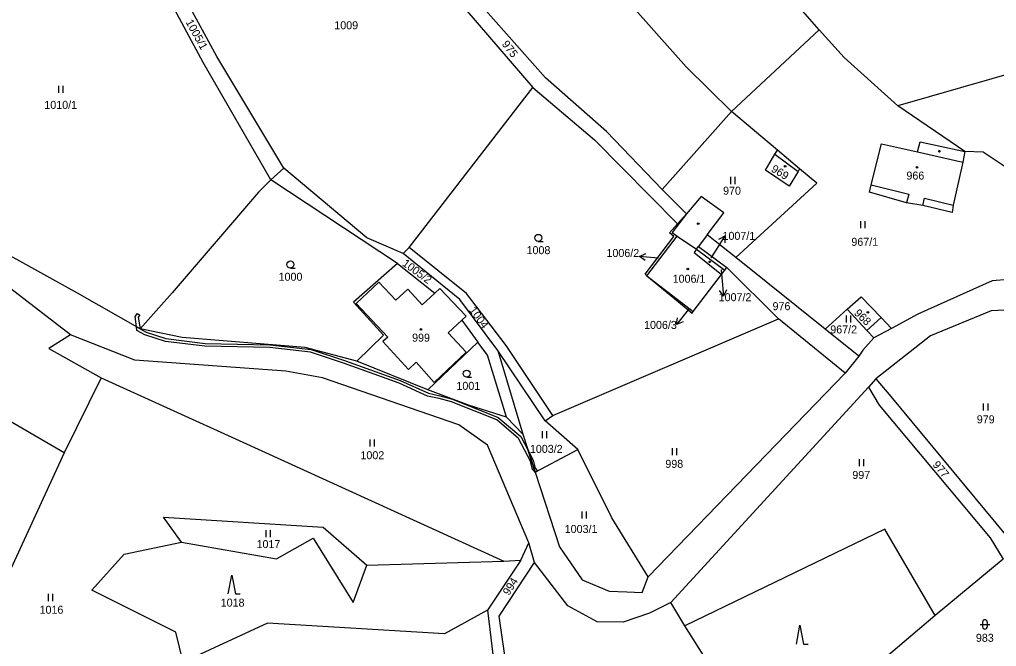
# Model space of a CAD drawing. Extents: x -670359 to -668019, y -978807 to -976674.
# Drawn here: x -669783.1 to -669575.5, y -977704.1 to -977570.9 of the extents above; entities that cross this region are included whole.
import ezdxf

# ---------------------------------------------------------------- set-up
doc = ezdxf.new("R2010")
doc.units = 0
for name, color, linetype in [('Hranice parcel', 7, 'Continuous'), ('Parcelní čísla', 7, 'Continuous'), ('Vnitřní kresba', 7, 'Continuous'), ('Věcná břemena k části', 7, 'Continuous'), ('Značky budov', 7, 'Continuous'), ('Značky kultur', 7, 'Continuous')]:
    doc.layers.add(name, color=color, linetype=linetype)

msp = doc.modelspace()

# ---------------------------------------------------------------- linework, layer by layer
at = {"layer": 'Hranice parcel'}
for p, q in [((-669702.8, -977622.71), (-669694.86, -977629.03)), ((-669694.86, -977629.03), (-669693.79, -977628.05)), ((-669693.79, -977628.05), (-669688.21, -977633.93)), ((-669688.21, -977633.93), (-669689.13, -977634.79)), ((-669689.13, -977634.79), (-669685.71, -977639.46))]:
    msp.add_line(p, q, dxfattribs=at)
for points in [[(-669741.19, -977578.75), (-669756.29, -977550.87)], [(-669613.14, -977573.11), (-669632.98, -977550.37)], [(-669744.06, -977580.04), (-669759.08, -977552.08)], [(-669641.45, -977580.95), (-669662.61, -977557.1)], [(-669690.63, -977565.98), (-669673.98, -977585.38)], [(-669671.35, -977583.28), (-669687.92, -977564.52)], [(-669631.8, -977590.48), (-669613.14, -977573.11)], [(-669607.88, -977578.99), (-669613.14, -977573.11)], [(-669729.69, -977604.97), (-669744.06, -977580.04)], [(-669726.9, -977602.47), (-669741.19, -977578.75)], [(-669596.46, -977589.23), (-669607.88, -977578.99)], [(-669563.17, -977579.68), (-669596.46, -977589.23)], [(-669631.8, -977590.48), (-669641.45, -977580.95)], [(-669658.33, -977594.71), (-669671.35, -977583.28)], [(-669700.29, -977619.32), (-669673.98, -977585.38)], [(-669673.98, -977585.38), (-669660.88, -977596.49)], [(-669631.8, -977590.48), (-669646.51, -977607.03)], [(-669622.05, -977598.67), (-669631.8, -977590.48)], [(-669582.18, -977598.97), (-669596.46, -977589.23)], [(-669646.51, -977607.03), (-669658.33, -977594.71)], [(-669660.88, -977596.49), (-669643.3, -977614.32)], [(-669592.25, -977599.03), (-669591.7, -977596.87)], [(-669591.7, -977596.87), (-669582.18, -977598.97)], [(-669622.56, -977599.53), (-669622.05, -977598.67)], [(-669617.33, -977602.63), (-669622.05, -977598.67)], [(-669602.13, -977606.04), (-669599.94, -977597.32)], [(-669599.94, -977597.32), (-669592.25, -977599.03)], [(-669582.18, -977598.97), (-669582.61, -977601.23)], [(-669578.34, -977599.11), (-669582.18, -977598.97)], [(-669546.47, -977620.34), (-669578.34, -977599.11)], [(-669624.54, -977602.9), (-669622.56, -977599.53)], [(-669582.61, -977601.23), (-669584.67, -977610.34)], [(-669729.69, -977604.97), (-669726.9, -977602.47)], [(-669709.26, -977617.28), (-669726.9, -977602.47)], [(-669619.56, -977606.31), (-669624.54, -977602.9)], [(-669617.66, -977603.18), (-669619.56, -977606.31)], [(-669617.33, -977602.63), (-669617.66, -977603.18)], [(-669613.65, -977605.71), (-669617.33, -977602.63)], [(-669729.69, -977604.97), (-669732.31, -977607.62)], [(-669702.8, -977622.71), (-669729.69, -977604.97)], [(-669641.36, -977612.19), (-669646.51, -977607.03)], [(-669630.9, -977621.45), (-669613.65, -977605.71)], [(-669602.44, -977607.57), (-669602.13, -977606.04)], [(-669732.31, -977607.62), (-669750.67, -977628.99)], [(-669638.26, -977608.5), (-669641.36, -977612.19)], [(-669633.45, -977611.99), (-669638.26, -977608.5)], [(-669594.59, -977609.84), (-669602.44, -977607.57)], [(-669591.15, -977610.45), (-669594.59, -977609.84)], [(-669584.91, -977611.94), (-669591.15, -977610.45)], [(-669584.67, -977610.34), (-669584.91, -977611.94)], [(-669641.36, -977612.19), (-669644.37, -977616.17)], [(-669643.3, -977614.32), (-669641.36, -977612.19)], [(-669636.94, -977616.64), (-669633.45, -977611.99)], [(-669644.94, -977616.21), (-669643.3, -977614.32)], [(-669701.58, -977620.62), (-669709.26, -977617.28)], [(-669650.15, -977625.03), (-669644.06, -977617)], [(-669649.75, -977625.36), (-669643.33, -977616.96)], [(-669644.06, -977617), (-669644.94, -977616.21)], [(-669644.37, -977616.17), (-669643.33, -977616.96)], [(-669636.94, -977616.64), (-669638.77, -977619.13)], [(-669630.9, -977621.45), (-669636.94, -977616.64)], [(-669770.74, -977629.03), (-669788.31, -977619.38)], [(-669701.58, -977620.62), (-669700.29, -977619.32)], [(-669688.13, -977629.14), (-669700.29, -977619.32)], [(-669639.2, -977619.73), (-669639.7, -977620.4), (-669633.91, -977625.07)], [(-669639.2, -977619.73), (-669638.77, -977619.13)], [(-669639.2, -977619.73), (-669633.19, -977624.13)], [(-669638.77, -977619.13), (-669632.78, -977623.59)], [(-669689.55, -977630.42), (-669701.58, -977620.62)], [(-669611.88, -977636.68), (-669630.9, -977621.45)], [(-669702.8, -977622.71), (-669712.12, -977630.99)], [(-669633.91, -977625.07), (-669633.19, -977624.13)], [(-669633.19, -977624.13), (-669632.78, -977623.59)], [(-669632.78, -977623.59), (-669621.84, -977634.48)], [(-669650.15, -977625.03), (-669649.75, -977625.36)], [(-669649.75, -977625.36), (-669644.66, -977629.57), (-669640.16, -977633.27)], [(-669649.75, -977625.36), (-669639.91, -977632.94)], [(-669639.91, -977632.94), (-669633.91, -977625.07)], [(-669562.52, -977625.31), (-669576.43, -977626.43)], [(-669772.22, -977637.91), (-669784.93, -977628.12)], [(-669576.43, -977626.43), (-669592.23, -977633.48)], [(-669757.47, -977636.62), (-669770.74, -977629.03)], [(-669750.67, -977628.99), (-669757.47, -977636.62)], [(-669679.67, -977640.17), (-669688.13, -977629.14)], [(-669607.19, -977632.45), (-669604.24, -977629.79)], [(-669604.24, -977629.79), (-669599.98, -977634.24)], [(-669712.12, -977630.99), (-669705.76, -977637.99)], [(-669681.42, -977641.23), (-669689.55, -977630.42)], [(-669564, -977632.19), (-669576.64, -977632.82)], [(-669669.73, -977655.05), (-669621.84, -977634.48)], [(-669640.16, -977633.27), (-669639.91, -977632.94)], [(-669607.67, -977646.03), (-669621.84, -977634.48)], [(-669611.88, -977636.68), (-669607.19, -977632.45)], [(-669603, -977636.98), (-669607.19, -977632.45)], [(-669599.98, -977634.24), (-669597.8, -977636.52)], [(-669592.23, -977633.48), (-669597.8, -977636.52)], [(-669576.64, -977632.82), (-669589.48, -977638.09)], [(-669597.8, -977636.52), (-669601.54, -977638.56)], [(-669772.22, -977637.91), (-669776.84, -977640.81)], [(-669758.59, -977643.26), (-669772.22, -977637.91)], [(-669748.54, -977638.48), (-669757.47, -977636.62)], [(-669722.38, -977640.57), (-669748.54, -977638.48)], [(-669705.76, -977637.99), (-669711.41, -977643.46)], [(-669604.71, -977642.43), (-669611.88, -977636.68)], [(-669601.54, -977638.56), (-669603.86, -977641.14)], [(-669601.54, -977638.56), (-669603, -977636.98)], [(-669589.48, -977638.09), (-669601.11, -977647.27)], [(-669716.21, -977642.21), (-669722.38, -977640.57)], [(-669685.71, -977639.46), (-669696.32, -977649.6)], [(-669683.67, -977642.25), (-669685.71, -977639.46)], [(-669669.73, -977655.05), (-669679.67, -977640.17)], [(-669773.6, -977662.93), (-669808.82, -977642.52)], [(-669776.84, -977640.81), (-669765.77, -977647.06)], [(-669711.41, -977643.46), (-669716.21, -977642.21)], [(-669679.6, -977655.41), (-669683.67, -977642.25)], [(-669671.39, -977656.17), (-669681.42, -977641.23)], [(-669681.42, -977641.23), (-669676.14, -977658.99)], [(-669604.71, -977642.43), (-669607.67, -977646.03)], [(-669603.86, -977641.14), (-669604.71, -977642.43)], [(-669726.51, -977645.62), (-669758.59, -977643.26)], [(-669696.32, -977649.6), (-669711.41, -977643.46)], [(-669718.67, -977647.02), (-669726.51, -977645.62)], [(-669607.67, -977646.03), (-669649.47, -977689.27)], [(-669765.77, -977647.06), (-669773.6, -977662.93)], [(-669765.77, -977647.06), (-669736.42, -977660.32)], [(-669689.74, -977656.99), (-669718.67, -977647.02)], [(-669602.7, -977649.04), (-669644.68, -977694.76)], [(-669601.11, -977647.27), (-669602.7, -977649.04)], [(-669602.7, -977649.04), (-669600.44, -977652.86)], [(-669601.11, -977647.27), (-669597.97, -977651.01)], [(-669687.45, -977652.9), (-669696.32, -977649.6)], [(-669597.97, -977651.01), (-669573.58, -977680.35)], [(-669679.6, -977655.41), (-669687.45, -977652.9)], [(-669600.44, -977652.86), (-669576.86, -977681.01)], [(-669671.39, -977656.17), (-669669.73, -977655.05)], [(-669683.64, -977661.35), (-669689.74, -977656.99)], [(-669676.14, -977658.99), (-669679.6, -977655.41)], [(-669664.46, -977662.23), (-669671.39, -977656.17)], [(-669676.14, -977658.99), (-669673.51, -977667.04)], [(-669736.42, -977660.32), (-669680.15, -977685.94)], [(-669674.89, -977682.08), (-669683.64, -977661.35)], [(-669773.6, -977662.93), (-669791.07, -977700.83)], [(-669673.51, -977667.04), (-669664.46, -977662.23)], [(-669657.23, -977676.79), (-669664.46, -977662.23)], [(-669673.51, -977667.04), (-669668.33, -977682.92)], [(-669748.63, -977681.96), (-669752.49, -977676.63)], [(-669752.49, -977676.63), (-669718.58, -977678.74)], [(-669649.47, -977689.27), (-669657.23, -977676.79)], [(-669718.58, -977678.74), (-669709.26, -977686.84)], [(-669599.18, -977679.15), (-669641.69, -977699.7)], [(-669588.52, -977697.54), (-669599.18, -977679.15)], [(-669760.85, -977684.51), (-669748.63, -977681.96)], [(-669748.63, -977681.96), (-669728.46, -977685.51)], [(-669728.46, -977685.51), (-669720.72, -977681.07)], [(-669720.72, -977681.07), (-669712.17, -977694.77)], [(-669676.55, -977685.76), (-669674.89, -977682.08)], [(-669673.67, -977686.22), (-669674.89, -977682.08)], [(-669576.86, -977681.01), (-669574.03, -977685.55)], [(-669668.33, -977682.92), (-669663.5, -977689.92)], [(-669767.69, -977692.14), (-669760.85, -977684.51)], [(-669709.26, -977686.84), (-669680.15, -977685.94)], [(-669676.55, -977685.76), (-669683.61, -977696.35)], [(-669681.13, -977697.62), (-669673.67, -977686.22)], [(-669680.15, -977685.94), (-669676.55, -977685.76)], [(-669666.58, -977695.45), (-669673.67, -977686.22)], [(-669574.03, -977685.55), (-669588.52, -977697.54)], [(-669712.17, -977694.77), (-669709.26, -977686.84)], [(-669663.5, -977689.92), (-669657.8, -977692.36)], [(-669650.77, -977692.64), (-669649.47, -977689.27)], [(-669749.88, -977701.06), (-669767.69, -977692.14)], [(-669657.8, -977692.36), (-669654.05, -977692.5)], [(-669654.05, -977692.5), (-669650.77, -977692.64)], [(-669683.61, -977696.35), (-669692.78, -977701.44)], [(-669683.61, -977696.35), (-669682.02, -977709.93)], [(-669660.33, -977698.85), (-669666.58, -977695.45)], [(-669644.68, -977694.76), (-669649.22, -977697.03)], [(-669641.69, -977699.7), (-669644.68, -977694.76)], [(-669679.55, -977708.95), (-669681.13, -977697.62)], [(-669654.81, -977698.9), (-669660.33, -977698.85)], [(-669649.22, -977697.03), (-669654.81, -977698.9)], [(-669588.52, -977697.54), (-669601.66, -977708.73)], [(-669730.38, -977699.11), (-669748.33, -977707.45)], [(-669692.78, -977701.44), (-669730.38, -977699.11)], [(-669624.67, -977726.69), (-669641.69, -977699.7)], [(-669748.33, -977707.45), (-669749.88, -977701.06)]]:
    msp.add_lwpolyline(points, dxfattribs=at)
at = {"layer": 'Parcelní čísla'}
for p, q in [((-669634.5, -977617.57), (-669633.17, -977616.87)), ((-669650.12, -977622.13), (-669651.36, -977621.29)), ((-669636.08, -977621.53), (-669635.29, -977620.26)), ((-669633.96, -977624.11), (-669633.83, -977625.72)), ((-669632.87, -977628.35), (-669633.52, -977629.71)), ((-669640.88, -977632.4), (-669641.02, -977632.58)), ((-669642.09, -977635.17), (-669643.48, -977635.73))]:
    msp.add_line(p, q, dxfattribs=at)
for points in [[(-669635.29, -977620.26), (-669633.17, -977616.87), (-669633.22, -977618.37)], [(-669647.37, -977621.58), (-669651.36, -977621.29), (-669650.01, -977620.64)], [(-669633.83, -977625.72), (-669633.52, -977629.71), (-669634.37, -977628.47)], [(-669641.02, -977632.58), (-669643.48, -977635.73), (-669643.27, -977634.25)]]:
    msp.add_lwpolyline(points, dxfattribs=at)
at = {"layer": 'Vnitřní kresba'}
for points in [[(-669592.25, -977599.03), (-669582.61, -977601.23)], [(-669622.56, -977599.53), (-669617.66, -977603.18)], [(-669602.13, -977606.04), (-669594.14, -977608.01)], [(-669594.14, -977608.01), (-669594.59, -977609.84)], [(-669591.15, -977610.45), (-669590.75, -977608.84)], [(-669590.75, -977608.84), (-669584.67, -977610.34)], [(-669643.33, -977616.96), (-669639.2, -977619.73)], [(-669711.53, -977631.23), (-669706.74, -977626.68)], [(-669706.74, -977626.68), (-669703.12, -977630.56), (-669700.6, -977628.22)], [(-669700.6, -977628.22), (-669697.54, -977631.53)], [(-669697.54, -977631.53), (-669694.86, -977629.03)], [(-669711.53, -977631.23), (-669704.83, -977638.4)], [(-669603, -977636.98), (-669599.98, -977634.24)], [(-669692.01, -977637.46), (-669689.13, -977634.79)], [(-669704.83, -977638.4), (-669705.85, -977639.3)], [(-669692.01, -977637.46), (-669688.16, -977641.61)], [(-669705.85, -977639.3), (-669700.4, -977645.23)], [(-669694.95, -977648.05), (-669688.16, -977641.61)], [(-669700.4, -977645.23), (-669698.82, -977643.73)], [(-669698.82, -977643.73), (-669694.95, -977648.05)]]:
    msp.add_lwpolyline(points, dxfattribs=at)
at = {"layer": 'Věcná břemena k části'}
for p, q in [((-669758.17, -977636.97), (-669758.25, -977636.17)), ((-669758.17, -977636.97), (-669758.25, -977636.17)), ((-669756.44, -977637.89), (-669758.17, -977636.97)), ((-669756.44, -977637.89), (-669758.17, -977636.97)), ((-669757.47, -977636.62), (-669756.2, -977637.33)), ((-669757.47, -977636.62), (-669756.2, -977637.33)), ((-669752.08, -977639.29), (-669756.44, -977637.89)), ((-669752.08, -977639.29), (-669756.44, -977637.89)), ((-669756.2, -977637.33), (-669751.96, -977638.71)), ((-669756.2, -977637.33), (-669751.96, -977638.71)), ((-669743.68, -977640.32), (-669752.08, -977639.29)), ((-669743.68, -977640.32), (-669752.08, -977639.29)), ((-669751.96, -977638.71), (-669743.64, -977639.72)), ((-669751.96, -977638.71), (-669743.64, -977639.72)), ((-669729.92, -977640.6), (-669743.68, -977640.32)), ((-669729.92, -977640.6), (-669743.68, -977640.32)), ((-669743.64, -977639.72), (-669729.88, -977640)), ((-669743.64, -977639.72), (-669729.88, -977640)), ((-669721.23, -977641.57), (-669729.92, -977640.6)), ((-669721.23, -977641.57), (-669729.92, -977640.6)), ((-669729.88, -977640), (-669721.11, -977640.99)), ((-669729.88, -977640), (-669721.11, -977640.99)), ((-669714.02, -977643.97), (-669721.23, -977641.57)), ((-669714.02, -977643.97), (-669721.23, -977641.57)), ((-669721.11, -977640.99), (-669713.82, -977643.41)), ((-669721.11, -977640.99), (-669713.82, -977643.41)), ((-669702.44, -977648.18), (-669714.02, -977643.97)), ((-669702.44, -977648.18), (-669714.02, -977643.97)), ((-669713.82, -977643.41), (-669702.22, -977647.62)), ((-669713.82, -977643.41), (-669702.22, -977647.62)), ((-669696.37, -977650.9), (-669702.44, -977648.18)), ((-669696.37, -977650.9), (-669702.44, -977648.18)), ((-669702.22, -977647.62), (-669696.19, -977650.32)), ((-669702.22, -977647.62), (-669696.19, -977650.32)), ((-669693.9, -977651.4), (-669696.37, -977650.9)), ((-669693.9, -977651.4), (-669696.37, -977650.9)), ((-669696.19, -977650.32), (-669693.76, -977650.82)), ((-669696.19, -977650.32), (-669693.76, -977650.82)), ((-669693.76, -977650.82), (-669691.1, -977651.58)), ((-669693.76, -977650.82), (-669691.1, -977651.58)), ((-669691.3, -977652.14), (-669693.9, -977651.4)), ((-669691.3, -977652.14), (-669693.9, -977651.4)), ((-669681.67, -977655.95), (-669691.3, -977652.14)), ((-669681.67, -977655.95), (-669691.3, -977652.14)), ((-669691.1, -977651.58), (-669681.35, -977655.43)), ((-669691.1, -977651.58), (-669681.35, -977655.43)), ((-669677.02, -977659.89), (-669681.67, -977655.95)), ((-669677.02, -977659.89), (-669681.67, -977655.95)), ((-669681.35, -977655.43), (-669676.54, -977659.51)), ((-669681.35, -977655.43), (-669676.54, -977659.51)), ((-669674.51, -977664.72), (-669677.02, -977659.89)), ((-669674.51, -977664.72), (-669677.02, -977659.89)), ((-669676.54, -977659.51), (-669675.01, -977662.47)), ((-669676.54, -977659.51), (-669675.01, -977662.47)), ((-669674.07, -977666.48), (-669674.51, -977664.72)), ((-669674.07, -977666.48), (-669674.51, -977664.72)), ((-669673.46, -977667.21), (-669674.07, -977666.48)), ((-669673.46, -977667.21), (-669674.07, -977666.48))]:
    msp.add_line(p, q, dxfattribs=at)
for points in [[(-669758.25, -977636.17), (-669758.48, -977634.01), (-669758.02, -977633.36), (-669757.53, -977633.71), (-669757.86, -977634.17), (-669757.47, -977636.62), (-669758.25, -977636.17)], [(-669758.25, -977636.17), (-669758.48, -977634.01), (-669758.02, -977633.36), (-669757.53, -977633.71), (-669757.86, -977634.17), (-669757.47, -977636.62), (-669758.25, -977636.17)], [(-669758.25, -977636.17), (-669757.47, -977636.62)], [(-669758.25, -977636.17), (-669757.47, -977636.62)], [(-669675.01, -977662.47), (-669673.46, -977667.21)], [(-669675.01, -977662.47), (-669673.95, -977664.5), (-669673.53, -977666.2), (-669673.03, -977666.79), (-669673.51, -977667.04), (-669675.01, -977662.47)], [(-669675.01, -977662.47), (-669673.46, -977667.21)]]:
    msp.add_lwpolyline(points, dxfattribs=at)
at = {"layer": 'Značky budov'}
for centre in [(-669620.4, -977602.11), (-669592.36, -977602.32), (-669641.08, -977623.92), (-669602.81, -977633.12), (-669697.77, -977636.75)]:
    msp.add_circle(centre, 0.175, dxfattribs=at)
at = {"layer": 'Značky kultur'}
for p, q in [((-669774.82, -977585), (-669774.82, -977586.5)), ((-669773.82, -977586.5), (-669773.82, -977585)), ((-669631.98, -977604.36), (-669631.98, -977605.86)), ((-669630.98, -977605.86), (-669630.98, -977604.36)), ((-669604.4, -977613.73), (-669604.4, -977615.23)), ((-669603.4, -977615.23), (-669603.4, -977613.73)), ((-669672.84, -977618.06), (-669671.84, -977618.06)), ((-669725.53, -977623.71), (-669724.53, -977623.71)), ((-669607.46, -977633.81), (-669607.46, -977635.31)), ((-669606.46, -977635.31), (-669606.46, -977633.81)), ((-669688.06, -977646.88), (-669687.06, -977646.88)), ((-669578.28, -977652.49), (-669578.28, -977653.99)), ((-669577.28, -977653.99), (-669577.28, -977652.49)), ((-669672.05, -977658.38), (-669672.05, -977659.88)), ((-669671.05, -977659.88), (-669671.05, -977658.38)), ((-669708.64, -977660.12), (-669708.64, -977661.62)), ((-669707.64, -977661.62), (-669707.64, -977660.12)), ((-669644.42, -977661.95), (-669644.42, -977663.45)), ((-669643.42, -977663.45), (-669643.42, -977661.95)), ((-669604.69, -977664.31), (-669604.69, -977665.81)), ((-669603.69, -977665.81), (-669603.69, -977664.31)), ((-669663.59, -977675.4), (-669663.59, -977676.9)), ((-669662.59, -977676.9), (-669662.59, -977675.4)), ((-669730.77, -977679.39), (-669730.77, -977680.89)), ((-669729.77, -977680.89), (-669729.77, -977679.39)), ((-669777, -977692.94), (-669777, -977694.44)), ((-669776, -977694.44), (-669776, -977692.94)), ((-669578.93, -977699.4), (-669576.93, -977699.4)), ((-669578.43, -977698.9), (-669578.43, -977699.9)), ((-669577.43, -977698.9), (-669577.43, -977699.9))]:
    msp.add_line(p, q, dxfattribs=at)
for points in [[(-669738.72, -977692.93), (-669737.97, -977688.93), (-669737.22, -977692.93), (-669736.22, -977692.93)], [(-669617.99, -977703.6), (-669617.24, -977699.6), (-669616.49, -977703.6), (-669615.49, -977703.6)]]:
    msp.add_lwpolyline(points, dxfattribs=at)
for centre, radius in [((-669587.62, -977598.9), 0.175), ((-669620.4, -977602.11), 0.175), ((-669592.36, -977602.32), 0.175), ((-669638.87, -977614.27), 0.175), ((-669672.84, -977617.31), 0.75), ((-669725.53, -977622.96), 0.75), ((-669641.08, -977623.92), 0.175), ((-669636.43, -977622.39), 0.175), ((-669602.81, -977633.12), 0.175), ((-669697.77, -977636.75), 0.175), ((-669688.06, -977646.13), 0.75)]:
    msp.add_circle(centre, radius, dxfattribs=at)
for centre, start, end in [((-669577.93, -977698.9), 0, 180), ((-669577.93, -977699.9), 180, 0)]:
    msp.add_arc(centre, 0.5, start, end, dxfattribs=at)

# ---------------------------------------------------------------- texts
at = {"layer": 'Parcelní čísla'}
for s, rotation, p in [('1005/1', 298.8196, (-669747.84, -977571.45)), ('975', 307.1041, (-669680.69, -977576.16)), ('969', 328.0999, (-669623.53, -977603.08)), ('1005/2', 323.5837, (-669701.89, -977623.04)), ('1004', 306.7097, (-669687.65, -977632.69)), ('968', 315.9935, (-669605.86, -977633.44)), ('977', 310.1148, (-669589.17, -977665.55)), ('994', 58.1361, (-669679.08, -977693.38))]:
    msp.add_text(s, height=1.7, rotation=rotation, dxfattribs=at).set_placement(p)
for s, height, p in [('1009', 1.7, (-669716.19, -977572.99)), ('1010/1', 1.7, (-669777.81, -977589.9)), ('966', 1.7, (-669594.62, -977604.92)), ('970', 1.7, (-669633.58, -977608.13)), ('1007/1', 1.7, (-669633.7, -977617.72)), ('967/1', 1.7, (-669606.32, -977618.99)), ('1008', 1.7, (-669675.34, -977620.76)), ('1006/2', 1.7, (-669658.36, -977621.36)), ('1006/2', 0.1, (-669647.37, -977621.58)), ('1007/1', 0.1, (-669636.08, -977621.53)), ('1007/2', 0.1, (-669633.96, -977624.11)), ('1000', 1.7, (-669728.03, -977626.41)), ('1006/1', 1.7, (-669644.29, -977626.83)), ('1007/2', 1.7, (-669634.52, -977630.75)), ('1006/3', 0.1, (-669640.88, -977632.4)), ('976', 1.7, (-669623.07, -977632.66)), ('1006/3', 1.7, (-669650.37, -977636.64)), ('967/2', 1.7, (-669610.8, -977637.6)), ('999', 1.7, (-669699.66, -977639.35)), ('1001', 1.7, (-669690.24, -977649.58)), ('979', 1.7, (-669579.67, -977656.69)), ('1003/2', 1.7, (-669674.63, -977662.97)), ('1002', 1.7, (-669710.64, -977664.32)), ('998', 1.7, (-669645.85, -977666.15)), ('997', 1.7, (-669606.12, -977668.51)), ('1003/1', 1.7, (-669667.23, -977679.98)), ('1017', 1.7, (-669732.72, -977683.19)), ('1018', 1.7, (-669740.33, -977695.63)), ('1016', 1.7, (-669778.82, -977697.14)), ('983', 1.7, (-669579.86, -977703.1))]:
    msp.add_text(s, height=height, dxfattribs=at).set_placement(p)

doc.saveas('drawing.dxf')
